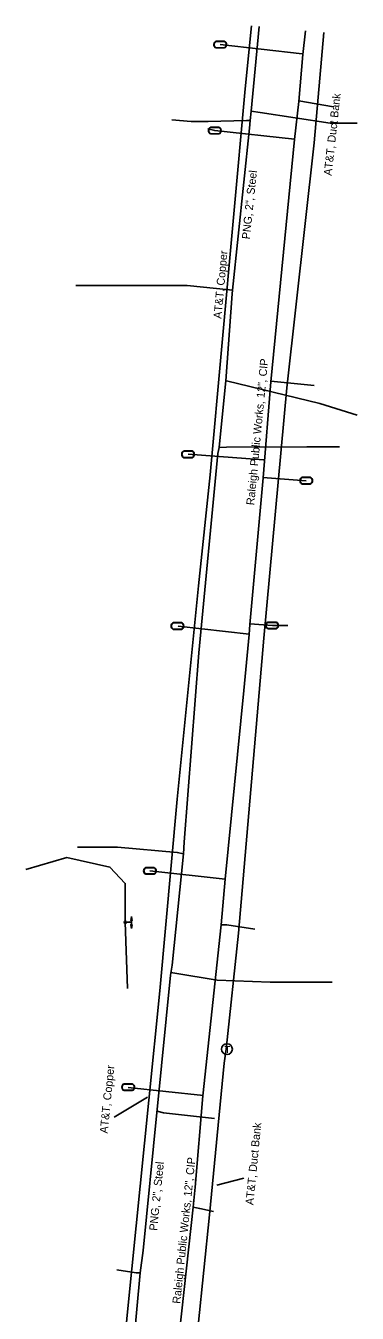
# Model space of a CAD drawing. Extents: x 2070721 to 2083340, y 729290 to 737883.
# Drawn here: x 2082371 to 2082537, y 737239 to 737883 of the extents above; entities that cross this region are included whole.
import ezdxf

# ---------------------------------------------------------------- set-up
doc = ezdxf.new("R2010")
doc.units = 0
for name, color, linetype in [('Exist Utilities Gas UG Line SUE LOS B', 7, 'Continuous'), ('Exist Utilities Gas UG Line SUE LOS B Text', 7, 'Continuous'), ('Exist Utilities Power Change of Service SUE CELL', 7, 'Continuous'), ('Exist Utilities Power UG Cable SUE LOS B', 7, 'Continuous'), ('Exist Utilities Power UG Cable SUE LOS C', 7, 'Continuous'), ('Exist Utilities Telephone Manhole CELL', 7, 'Continuous'), ('Exist Utilities Telephone UG Cable SUE LOS C', 7, 'Continuous'), ('Exist Utilities Telephone UG Cable SUE LOS C Leader', 7, 'Continuous'), ('Exist Utilities Telephone UG Cable SUE LOS C Text', 7, 'Continuous'), ('Exist Utilities Telephone UG Conduit SUE LOS B', 7, 'Continuous'), ('Exist Utilities Telephone UG FO SUE LOS B Leader', 7, 'Continuous'), ('Exist Utilities Telephone UG FO SUE LOS B Text', 7, 'Continuous'), ('Exist Utilities Water Meter CELL', 7, 'Continuous'), ('Exist Utilities Water UG Line SUE LOS B', 7, 'Continuous'), ('Exist Utilities Water UG Line SUE LOS B Text', 7, 'Continuous')]:
    doc.layers.add(name, color=color, linetype=linetype)

msp = doc.modelspace()

# ---------------------------------------------------------------- linework, layer by layer
at = {"layer": 'Exist Utilities Gas UG Line SUE LOS B'}
for points in [[(2082487.59, 737882.13), (2082483.51, 737839.88), (2082483, 737835.22)], [(2082536.52, 737833.77), (2082522.97, 737833.77), (2082487.98, 737839.16), (2082483.51, 737839.88)], [(2082483, 737835.22), (2082481.24, 737835.18), (2082462.05, 737834.7), (2082453.63, 737834.7), (2082443.84, 737835.54)], [(2082483, 737835.22), (2082482.63, 737831.3), (2082474.13, 737750.41), (2082474.03, 737748.58)], [(2082474.13, 737750.41), (2082472.68, 737750.56), (2082451.49, 737752.71), (2082424.37, 737752.71), (2082395.96, 737752.71)], [(2082470.85, 737705.09), (2082474.03, 737748.58)], [(2082470.85, 737705.09), (2082470.63, 737703.53), (2082467.59, 737671.86)], [(2082470.85, 737705.09), (2082471.19, 737705.01), (2082517.76, 737693.69), (2082536.4, 737687.88)], [(2082449.64, 737468.69), (2082450.03, 737474.55), (2082457.42, 737569.15), (2082466.95, 737668.72), (2082467.59, 737671.86)], [(2082467.59, 737671.86), (2082471.2, 737671.88), (2082511.29, 737672.07), (2082527.62, 737672.07)], [(2082449.64, 737468.69), (2082446.6, 737469.5), (2082416.78, 737472.17), (2082396.83, 737472.17)], [(2082443.22, 737408.08), (2082444.08, 737413.12), (2082449.64, 737468.69)], [(2082443.22, 737408.08), (2082436.59, 737340.96), (2082436.42, 737339.48)], [(2082523.95, 737404.6), (2082493.06, 737404.6), (2082466.47, 737405.71), (2082445.45, 737409.06), (2082443.45, 737409.42)], [(2082436.42, 737339.48), (2082429.5, 737270.55), (2082428.12, 737259.46)], [(2082436.5, 737340.22), (2082439.81, 737339.38), (2082465.16, 737336.53)], [(2082410, 737077.78), (2082411.36, 737086.72), (2082416.51, 737136.35), (2082423.37, 737208.61), (2082428.12, 737259.46)], [(2082428.12, 737259.46), (2082426.14, 737259.33), (2082416.35, 737260.83)]]:
    msp.add_lwpolyline(points, dxfattribs=at)
at = {"layer": 'Exist Utilities Power Change of Service SUE CELL'}
for p, q in [((2082420.64, 737434.54), (2082423.72, 737434.54)), ((2082420.64, 737434.54), (2082420.64, 737434.54)), ((2082423.72, 737431.4), (2082423.72, 737437.37)), ((2082423.72, 737434.54), (2082423.72, 737431.4))]:
    msp.add_line(p, q, dxfattribs=at)
for points in [[(2082423.72, 737431.4), (2082423.38, 737433.37), (2082423.72, 737432.95), (2082424.03, 737433.34)], [(2082423.72, 737437.37), (2082424.06, 737435.4), (2082423.72, 737435.82), (2082423.42, 737435.43)]]:
    msp.add_lwpolyline(points, close=True, dxfattribs=at)
msp.add_circle((2082420.64, 737434.54), 0.517, dxfattribs=at)
at = {"layer": 'Exist Utilities Power UG Cable SUE LOS B'}
msp.add_lwpolyline([(2082421.76, 737401.42), (2082420.64, 737434.54), (2082422.94, 737434.86)], dxfattribs=at)
at = {"layer": 'Exist Utilities Power UG Cable SUE LOS C'}
msp.add_lwpolyline([(2082420.64, 737434.54), (2082420.64, 737453.94), (2082412.95, 737462.12), (2082391.51, 737466.92), (2082370.92, 737460.99)], dxfattribs=at)
at = {"layer": 'Exist Utilities Telephone Manhole CELL'}
msp.add_circle((2082471.41, 737371.18), 2.72, dxfattribs=at)
at = {"layer": 'Exist Utilities Telephone UG Cable SUE LOS C'}
msp.add_lwpolyline([(2082403.44, 737082.03), (2082412.57, 737137.7), (2082418.97, 737209.91), (2082421.82, 737239.88), (2082432.43, 737345.64), (2082437.88, 737400.24), (2082446.55, 737496.08), (2082457.15, 737602.73), (2082463.04, 737658.16), (2082480.56, 737850.96), (2082483.62, 737882.51)], dxfattribs=at)
at = {"layer": 'Exist Utilities Telephone UG Cable SUE LOS C Leader'}
msp.add_line((2082431.74, 737347.15), (2082415.02, 737337.25), dxfattribs=at)
at = {"layer": 'Exist Utilities Telephone UG Conduit SUE LOS B'}
msp.add_lwpolyline([(2082440.99, 737055.64), (2082446.34, 737107.79), (2082451.46, 737177.85), (2082462.75, 737288.32), (2082470.03, 737364.09), (2082470.98, 737371.16), (2082477.18, 737429.09), (2082489.87, 737576.45), (2082501.4, 737701.55), (2082515.01, 737823.97), (2082519.76, 737879.1)], dxfattribs=at)
at = {"layer": 'Exist Utilities Telephone UG FO SUE LOS B Leader'}
msp.add_line((2082466.3, 737303.28), (2082479.79, 737306.7), dxfattribs=at)
at = {"layer": 'Exist Utilities Water Meter CELL'}
for p, q in [((2082468.04, 737873.1), (2082468.04, 737873.1)), ((2082465.38, 737830.14), (2082465.38, 737830.14)), ((2082451.98, 737668.4), (2082451.98, 737668.4)), ((2082511.04, 737655.21), (2082511.04, 737655.21)), ((2082446.7, 737582.59), (2082446.7, 737582.59)), ((2082493.96, 737582.86), (2082493.96, 737582.86)), ((2082432.96, 737460.25), (2082432.96, 737460.25)), ((2082422.1, 737352.17), (2082422.1, 737352.17))]:
    msp.add_line(p, q, dxfattribs=at)
for points in [[(2082470.08, 737871.54), (2082465.98, 737871.54)], [(2082470.08, 737871.4), (2082465.98, 737871.4)], [(2082466.01, 737874.8), (2082470.08, 737874.8)], [(2082466.01, 737874.66), (2082470.08, 737874.66)], [(2082463.34, 737831.84), (2082467.41, 737831.84)], [(2082463.34, 737831.7), (2082467.41, 737831.7)], [(2082467.41, 737828.58), (2082463.31, 737828.58)], [(2082467.41, 737828.44), (2082463.31, 737828.44)], [(2082449.94, 737670.1), (2082454.02, 737670.1)], [(2082449.94, 737669.97), (2082454.02, 737669.97)], [(2082454.02, 737666.84), (2082449.92, 737666.84)], [(2082454.02, 737666.7), (2082449.92, 737666.7)], [(2082509, 737656.91), (2082513.08, 737656.91)], [(2082509, 737656.77), (2082513.08, 737656.77)], [(2082513.08, 737653.65), (2082508.98, 737653.65)], [(2082513.08, 737653.51), (2082508.98, 737653.51)], [(2082448.74, 737581.03), (2082444.64, 737581.03)], [(2082448.74, 737580.89), (2082444.64, 737580.89)], [(2082444.66, 737584.29), (2082448.74, 737584.29)], [(2082444.66, 737584.15), (2082448.74, 737584.15)], [(2082496, 737581.29), (2082491.9, 737581.29)], [(2082496, 737581.16), (2082491.9, 737581.16)], [(2082491.92, 737584.56), (2082496, 737584.56)], [(2082491.92, 737584.42), (2082496, 737584.42)], [(2082435, 737458.69), (2082430.9, 737458.69)], [(2082435, 737458.55), (2082430.9, 737458.55)], [(2082430.92, 737461.95), (2082435, 737461.95)], [(2082430.92, 737461.82), (2082435, 737461.82)], [(2082420.06, 737353.87), (2082424.14, 737353.87)], [(2082424.14, 737350.61), (2082420.04, 737350.61)], [(2082424.14, 737350.47), (2082420.04, 737350.47)], [(2082420.06, 737353.73), (2082424.14, 737353.73)]]:
    msp.add_lwpolyline(points, dxfattribs=at)
for centre, radius, start, end in [((2082466.74, 737873.09), 1.86, 113.17804, 245.97939), ((2082466.75, 737873.09), 1.73, 115.30093, 243.78236), ((2082469.34, 737873.1), 1.86, 293.64832, 66.30838), ((2082469.35, 737873.1), 1.73, 295.12717, 64.87283), ((2082464.07, 737830.13), 1.86, 113.17804, 245.97939), ((2082464.08, 737830.13), 1.73, 115.30093, 243.78236), ((2082466.67, 737830.14), 1.86, 293.64832, 66.30838), ((2082466.68, 737830.14), 1.73, 295.12717, 64.87283), ((2082450.67, 737668.4), 1.86, 113.17804, 245.97939), ((2082450.68, 737668.4), 1.73, 115.30093, 243.78236), ((2082453.27, 737668.4), 1.86, 293.64832, 66.30838), ((2082453.28, 737668.4), 1.73, 295.12717, 64.87283), ((2082509.73, 737655.2), 1.86, 113.17804, 245.97939), ((2082509.74, 737655.2), 1.73, 115.30093, 243.78236), ((2082512.33, 737655.21), 1.86, 293.64832, 66.30838), ((2082512.34, 737655.21), 1.73, 295.12717, 64.87283), ((2082445.39, 737582.58), 1.86, 113.17804, 245.97939), ((2082445.4, 737582.58), 1.73, 115.30093, 243.78236), ((2082447.99, 737582.59), 1.86, 293.64832, 66.30838), ((2082448.01, 737582.59), 1.73, 295.12717, 64.87283), ((2082492.65, 737582.85), 1.86, 113.17804, 245.97939), ((2082492.66, 737582.85), 1.73, 115.30093, 243.78236), ((2082495.25, 737582.86), 1.86, 293.64832, 66.30838), ((2082495.27, 737582.86), 1.73, 295.12717, 64.87283), ((2082431.65, 737460.25), 1.86, 113.17804, 245.97939), ((2082431.67, 737460.25), 1.73, 115.30093, 243.78236), ((2082434.25, 737460.25), 1.86, 293.64832, 66.30838), ((2082434.27, 737460.25), 1.73, 295.12717, 64.87283), ((2082420.79, 737352.17), 1.86, 113.17804, 245.97939), ((2082423.39, 737352.17), 1.86, 293.64832, 66.30838), ((2082420.8, 737352.17), 1.73, 115.30093, 243.78236), ((2082423.41, 737352.17), 1.73, 295.12717, 64.87283)]:
    msp.add_arc(centre, radius, start, end, dxfattribs=at)
at = {"layer": 'Exist Utilities Water UG Line SUE LOS B'}
for p, q in [((2082468.06, 737873.13), (2082509.02, 737868.45)), ((2082524.7, 737842.03), (2082507.32, 737845.03)), ((2082514.95, 737702.79), (2082493.35, 737704.86)), ((2082489.64, 737665.56), (2082451.98, 737668.37)), ((2082511.02, 737655.15), (2082489.28, 737656.77)), ((2082447.04, 737582.55), (2082482.45, 737578.5)), ((2082432.97, 737460.24), (2082470.51, 737456.09)), ((2082459.64, 737347.95), (2082422.09, 737352.01))]:
    msp.add_line(p, q, dxfattribs=at)
for points in [[(2082454.53, 737292.18), (2082455.59, 737302.27), (2082459.43, 737347.81), (2082468.52, 737433.35), (2082470.51, 737456.11), (2082479.78, 737550.43), (2082482.45, 737578.36), (2082482.92, 737583.28), (2082489.45, 737656.68), (2082493.42, 737704.6), (2082505.09, 737825.65), (2082507.37, 737844.71), (2082509.28, 737868.07), (2082510.7, 737879.95)], [(2082461.84, 737830.96), (2082465.36, 737830.15), (2082505.11, 737825.87)], [(2082501.85, 737582.83), (2082494.1, 737582.84), (2082482.93, 737583.74)], [(2082485.39, 737431.2), (2082471.37, 737433.34), (2082468.52, 737433.35)], [(2082443.82, 737190.2), (2082444.22, 737192.46), (2082447.74, 737229.76), (2082454.53, 737292.18)], [(2082454.53, 737292.18), (2082457.83, 737291.52), (2082464.79, 737290.13)]]:
    msp.add_lwpolyline(points, dxfattribs=at)

# ---------------------------------------------------------------- texts
at = {"layer": 'Exist Utilities Gas UG Line SUE LOS B Text'}
for rotation, p in [(83.99685, (2082482.82, 737775.68)), (84.26949, (2082436.51, 737280.3))]:
    msp.add_text('PNG, 2", Steel', height=4, rotation=rotation, dxfattribs=at).set_placement(p)
at = {"layer": 'Exist Utilities Telephone Manhole CELL'}
msp.add_text('T', height=3.5, dxfattribs=at).set_placement((2082470.23, 737369.17))
at = {"layer": 'Exist Utilities Telephone UG Cable SUE LOS C Text'}
for rotation, p in [(84.80855, (2082468.66, 737735.97)), (84.27066, (2082411.8, 737328.92))]:
    msp.add_text('AT&T, Copper', height=4, rotation=rotation, dxfattribs=at).set_placement(p)
at = {"layer": 'Exist Utilities Telephone UG FO SUE LOS B Text'}
for rotation, p in [(83.65695, (2082523.69, 737807.43)), (84.51155, (2082484.63, 737293.14))]:
    msp.add_text('AT&T, Duct Bank', height=4, rotation=rotation, dxfattribs=at).set_placement(p)
at = {"layer": 'Exist Utilities Water UG Line SUE LOS B Text'}
for s, rotation, p in [('Raleigh Public Works, 12", CIP', 84.49581, (2082485.02, 737642.8)), ('Raleigh Public Works, 12", CIP ', 84.02989, (2082448.1, 737243.82))]:
    msp.add_text(s, height=4, rotation=rotation, dxfattribs=at).set_placement(p)

doc.saveas('drawing.dxf')
